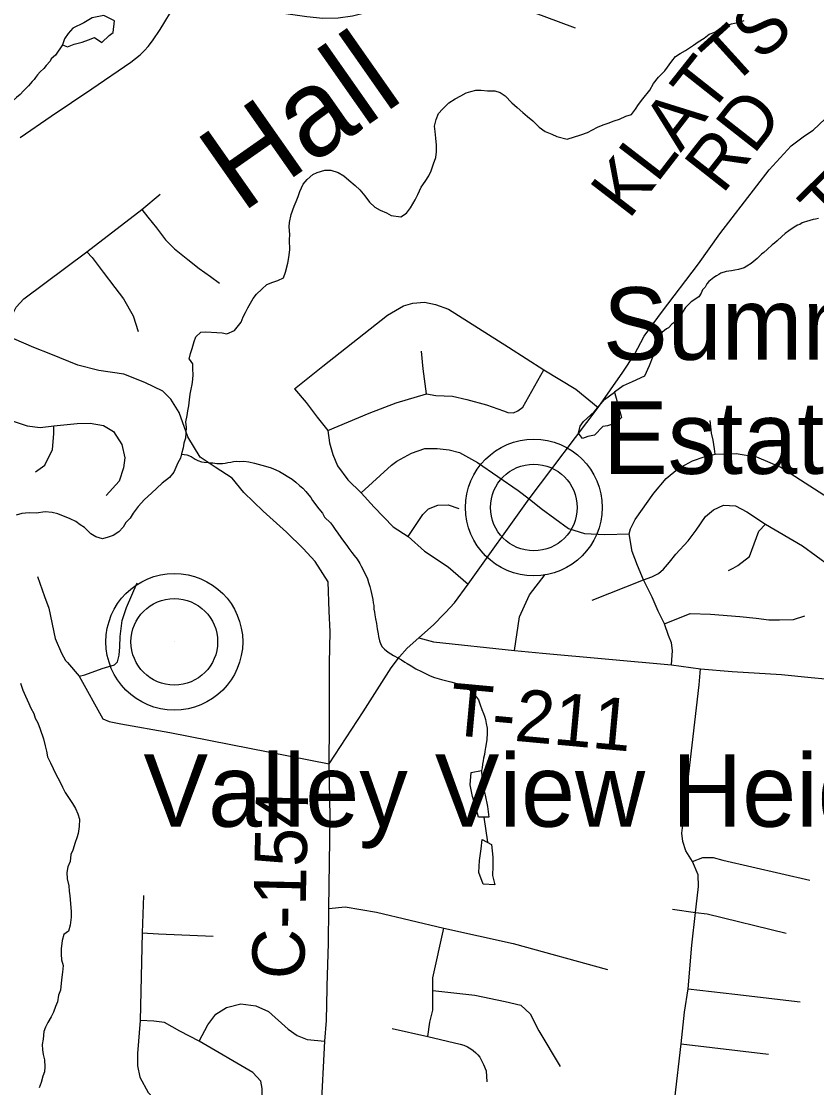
# Model space of a CAD drawing. Extents: x 0 to 34, y 0 to 22.
# Drawn here: x 6.213 to 6.645, y 17.164 to 17.744 of the extents above; entities that cross this region are included whole.
import ezdxf

# ---------------------------------------------------------------- set-up
doc = ezdxf.new("R2010")
doc.units = 0
for name, color, linetype in [('GM_X_County_Road', 7, 'Continuous'), ('GM_X_County_Road_Text', 7, 'Continuous'), ('GM_X_Minor_Lake', 7, 'Continuous'), ('GM_X_Minor_River', 7, 'Continuous'), ('GM_X_Minor_River_Text', 7, 'Continuous'), ('GM_X_Township_Road', 7, 'Continuous'), ('GM_X_Township_Road_Text', 7, 'Continuous'), ('GM_X_Unincorporated', 7, 'Continuous'), ('GM_X_Unincorporated_Location', 7, 'Continuous'), ('GM_X_Unincorporated_Text', 7, 'Continuous')]:
    doc.layers.add(name, color=color, linetype=linetype)

msp = doc.modelspace()

# ---------------------------------------------------------------- linework, layer by layer
at = {"layer": 'GM_X_County_Road'}
for points in [[(6.21206, 17.68092), (6.22902, 17.69252), (6.25117, 17.70742), (6.27244, 17.72194), (6.27744, 17.72589), (6.27986, 17.72827), (6.28173, 17.73042), (6.2842, 17.73355), (6.28826, 17.73975), (6.29651, 17.75325)], [(6.38018, 17.34004), (6.38051, 17.36122), (6.38051, 17.39483), (6.38074, 17.41186), (6.38029, 17.42306), (6.37962, 17.43919), (6.37267, 17.45017), (6.36617, 17.45734), (6.35712, 17.46614), (6.34443, 17.47751), (6.33388, 17.48773), (6.32745, 17.49547), (6.31819, 17.5016), (6.31001, 17.50705), (6.30333, 17.51798), (6.29861, 17.53124), (6.29416, 17.53849), (6.28971, 17.54294), (6.27998, 17.54756), (6.26861, 17.55217), (6.25493, 17.55415), (6.24356, 17.55712), (6.22889, 17.56305), (6.21966, 17.56668), (6.20325, 17.57373)], [(6.3792, 17.21796), (6.37922, 17.21894), (6.37984, 17.24247), (6.38003, 17.26136), (6.38077, 17.31122), (6.38018, 17.34004)], [(6.37235, 17.01941), (6.37239, 17.02043), (6.37207, 17.03968), (6.37221, 17.04345), (6.37333, 17.08511), (6.37333, 17.09592), (6.37376, 17.106), (6.37506, 17.13841), (6.37592, 17.15022), (6.37783, 17.18906), (6.37876, 17.20036), (6.3792, 17.21796)]]:
    msp.add_lwpolyline(points, dxfattribs=at)
at = {"layer": 'GM_X_Minor_Lake'}
msp.add_line((6.46432, 17.31097), (6.46634, 17.29737), dxfattribs=at)
for points in [[(6.26347, 17.74441), (6.25763, 17.74738), (6.25133, 17.74618), (6.24672, 17.74342), (6.24077, 17.7405), (6.23824, 17.73752), (6.23628, 17.73471), (6.23526, 17.7315), (6.2379, 17.7303), (6.24154, 17.73175), (6.24593, 17.7328), (6.24937, 17.73406), (6.25263, 17.73532), (6.25657, 17.73277), (6.26063, 17.73648), (6.26276, 17.73815), (6.26347, 17.74441)], [(6.53539, 17.54227), (6.53929, 17.52851), (6.536, 17.52553), (6.53161, 17.5241), (6.52913, 17.52358), (6.52467, 17.51892), (6.52105, 17.51823), (6.51799, 17.51715), (6.51596, 17.52005), (6.51679, 17.52383), (6.51855, 17.52646)], [(6.51855, 17.52646), (6.52435, 17.53166), (6.53, 17.53839), (6.53539, 17.54227)], [(6.46306, 17.33643), (6.46355, 17.32951), (6.46513, 17.32302), (6.46633, 17.31691), (6.46716, 17.31101), (6.46147, 17.31093), (6.46023, 17.31571), (6.45827, 17.32221), (6.45688, 17.3287), (6.45759, 17.33534)], [(6.4635, 17.29891), (6.46858, 17.29615), (6.4692, 17.2893), (6.46929, 17.28435), (6.46919, 17.27922), (6.47042, 17.27426), (6.46397, 17.27458), (6.46163, 17.2809), (6.46195, 17.28735), (6.46302, 17.29379)]]:
    msp.add_lwpolyline(points, dxfattribs=at)
at = {"layer": 'GM_X_Minor_River'}
for p, q in [((6.45759, 17.33534), (6.46306, 17.33643)), ((6.46302, 17.29379), (6.4635, 17.29891))]:
    msp.add_line(p, q, dxfattribs=at)
for points in [[(6.54465, 17.6935), (6.54698, 17.69631), (6.54854, 17.69894), (6.55087, 17.70194), (6.55475, 17.70681), (6.55672, 17.71039), (6.55943, 17.71376), (6.56291, 17.71731), (6.56661, 17.72257), (6.56874, 17.725), (6.57123, 17.72667), (6.57411, 17.72833), (6.57852, 17.73129), (6.58102, 17.73296), (6.58428, 17.73499), (6.58697, 17.73723), (6.59003, 17.73832), (6.59349, 17.74092), (6.59654, 17.742), (6.59921, 17.74291), (6.60245, 17.74361), (6.60607, 17.74469)], [(6.23526, 17.7315), (6.23142, 17.72576), (6.22909, 17.72374), (6.22849, 17.72261), (6.22634, 17.7202), (6.22497, 17.71853), (6.22302, 17.71669), (6.22165, 17.71502), (6.22048, 17.71372), (6.21969, 17.7126), (6.21871, 17.71149), (6.21675, 17.70907), (6.21402, 17.7063), (6.21207, 17.70445), (6.21013, 17.7028), (6.20838, 17.70113), (6.2074, 17.70002), (6.20661, 17.69872), (6.20486, 17.69686)], [(6.30407, 17.56026), (6.30489, 17.56348), (6.3057, 17.56612), (6.30672, 17.56991), (6.30771, 17.57255), (6.31041, 17.57497), (6.31307, 17.57512), (6.31913, 17.57482), (6.32197, 17.57458), (6.32462, 17.57416), (6.32882, 17.57599), (6.33232, 17.58049), (6.3335, 17.58332), (6.33469, 17.58576), (6.33606, 17.58821), (6.33899, 17.59329), (6.34075, 17.59573), (6.34364, 17.59834), (6.34634, 17.60095), (6.34959, 17.60223), (6.35226, 17.60313), (6.35532, 17.6046), (6.35651, 17.60762), (6.35774, 17.61254), (6.35836, 17.61557), (6.35882, 17.61974), (6.35873, 17.62525), (6.35878, 17.6281), (6.35847, 17.63228), (6.35871, 17.63475), (6.35955, 17.6391), (6.36114, 17.64364), (6.36233, 17.64609), (6.36333, 17.64892), (6.36432, 17.65156), (6.3661, 17.65552), (6.36823, 17.65814), (6.37132, 17.66075), (6.3738, 17.66185), (6.37781, 17.66311), (6.38122, 17.66324), (6.38518, 17.66184), (6.38818, 17.66008), (6.39098, 17.65775), (6.39434, 17.65485), (6.39695, 17.65252), (6.39974, 17.64924), (6.40214, 17.64578), (6.40513, 17.64307), (6.40794, 17.6415), (6.41152, 17.63992), (6.41396, 17.63855), (6.41925, 17.6377), (6.42232, 17.63974), (6.42446, 17.64274), (6.427, 17.64707), (6.42857, 17.64989), (6.43035, 17.65385), (6.4325, 17.65704), (6.43445, 17.66005), (6.43582, 17.66288), (6.43703, 17.66665), (6.43823, 17.67005), (6.43866, 17.67309), (6.43873, 17.67688), (6.43823, 17.68069), (6.43792, 17.68431), (6.43759, 17.68716), (6.43842, 17.69076), (6.4398, 17.69396), (6.44193, 17.6964), (6.44541, 17.69976), (6.44886, 17.70198), (6.45192, 17.70364), (6.4548, 17.7053), (6.45728, 17.70601), (6.46013, 17.70672), (6.46298, 17.70668), (6.46639, 17.70643), (6.47037, 17.70636), (6.4732, 17.70555), (6.476, 17.7036), (6.47954, 17.69993), (6.48252, 17.69722), (6.4857, 17.69451), (6.48813, 17.69238), (6.49112, 17.69004), (6.49447, 17.68657), (6.49784, 17.68423), (6.50142, 17.68284), (6.50405, 17.68146), (6.50971, 17.68004), (6.51715, 17.68238), (6.52077, 17.68365), (6.52632, 17.68659), (6.52938, 17.68787), (6.53205, 17.68877), (6.5353, 17.69005), (6.53816, 17.69095), (6.5416, 17.6926), (6.54465, 17.6935)], [(6.64639, 17.63693), (6.64486, 17.63659), (6.64353, 17.63625), (6.63989, 17.63521), (6.63874, 17.63486), (6.63759, 17.63451), (6.63624, 17.6336), (6.63509, 17.63325), (6.63317, 17.63216), (6.63027, 17.63015), (6.62833, 17.62868), (6.62658, 17.62702), (6.62405, 17.62481), (6.6225, 17.62352), (6.62134, 17.6226), (6.61861, 17.62002), (6.61667, 17.61836), (6.61551, 17.61744), (6.61317, 17.61504), (6.60988, 17.61247), (6.60756, 17.61101), (6.60602, 17.6101), (6.60295, 17.60905), (6.60086, 17.60872), (6.59914, 17.60839), (6.59761, 17.60824), (6.59628, 17.60808), (6.59341, 17.60721), (6.59225, 17.60648), (6.5909, 17.60576), (6.58955, 17.60484), (6.58684, 17.60264), (6.58566, 17.60134), (6.58486, 17.59947), (6.5833, 17.59799), (6.58269, 17.5963), (6.58131, 17.59425), (6.57725, 17.59151), (6.57413, 17.58836), (6.57255, 17.58594), (6.57193, 17.58406), (6.56864, 17.58149), (6.56784, 17.58018), (6.56669, 17.57945), (6.56493, 17.57741), (6.56377, 17.57687), (6.56261, 17.57595), (6.56145, 17.57504), (6.56027, 17.57355), (6.55928, 17.57187), (6.55846, 17.56961), (6.55762, 17.5666), (6.55722, 17.56547), (6.55699, 17.56396), (6.55658, 17.56283), (6.55636, 17.5617)], [(6.30407, 17.56026), (6.30595, 17.55772), (6.30588, 17.55488), (6.30599, 17.55202), (6.30592, 17.54917), (6.30547, 17.54652), (6.30503, 17.54406), (6.30439, 17.54123), (6.30412, 17.53819), (6.30366, 17.53497), (6.30321, 17.53213), (6.30276, 17.52968), (6.30211, 17.52627), (6.3024, 17.52303), (6.30233, 17.52018), (6.30207, 17.51734), (6.30123, 17.51451), (6.30079, 17.51205), (6.29995, 17.50884), (6.29932, 17.50638), (6.29793, 17.50395), (6.29692, 17.50131), (6.29572, 17.49888), (6.29336, 17.4959), (6.28931, 17.49277), (6.28367, 17.48741), (6.27979, 17.4839), (6.27629, 17.48019), (6.27354, 17.47646), (6.27195, 17.47384), (6.26962, 17.47143), (6.26822, 17.4688), (6.26589, 17.46639), (6.2628, 17.46438), (6.25994, 17.46351), (6.25688, 17.46245), (6.25331, 17.46368), (6.25051, 17.46528), (6.24718, 17.4686), (6.24476, 17.47018), (6.24234, 17.47195), (6.23935, 17.47336), (6.2326, 17.4762), (6.22958, 17.47685), (6.2258, 17.47714), (6.22086, 17.47651), (6.21707, 17.47661), (6.21309, 17.47634), (6.21003, 17.47547)], [(6.55636, 17.5617), (6.55429, 17.55672), (6.55189, 17.55106), (6.545, 17.54797), (6.54021, 17.54579), (6.53539, 17.54227)], [(6.2999, 17.50865), (6.30284, 17.50824), (6.30511, 17.50725), (6.30737, 17.50588), (6.30887, 17.50509), (6.31076, 17.50449), (6.31228, 17.50427), (6.31437, 17.50404), (6.3157, 17.50383), (6.31703, 17.5038), (6.31911, 17.50358), (6.32215, 17.50352), (6.32368, 17.50369), (6.3252, 17.50404), (6.32673, 17.5042), (6.32825, 17.50456), (6.32978, 17.50472), (6.33168, 17.50469), (6.33377, 17.50484), (6.33661, 17.50441), (6.33965, 17.50379), (6.3457, 17.50216), (6.34873, 17.50116), (6.35118, 17.50016), (6.35325, 17.49918), (6.36003, 17.49506), (6.36209, 17.49331), (6.36415, 17.49157), (6.36584, 17.49002), (6.36752, 17.48827), (6.3692, 17.48634), (6.37031, 17.48499), (6.37124, 17.48345), (6.37458, 17.47883), (6.37663, 17.47651), (6.37774, 17.4744), (6.38092, 17.4713), (6.38203, 17.46976), (6.38352, 17.46764), (6.385, 17.46553), (6.38667, 17.46321), (6.38797, 17.46129), (6.38983, 17.45897), (6.39095, 17.45724), (6.39262, 17.45512), (6.39392, 17.45339), (6.39541, 17.45146), (6.39689, 17.44915), (6.39763, 17.44762), (6.39855, 17.44608), (6.40112, 17.44071), (6.40166, 17.4388), (6.40238, 17.4365), (6.40291, 17.4344), (6.40397, 17.42944), (6.40413, 17.42772), (6.40449, 17.4262), (6.40464, 17.42429), (6.405, 17.42257), (6.40516, 17.42124), (6.40551, 17.41895), (6.40603, 17.41647), (6.40637, 17.41361), (6.40689, 17.41075), (6.40706, 17.40941), (6.40758, 17.40693), (6.40831, 17.40502), (6.40905, 17.40367), (6.41036, 17.40251), (6.41242, 17.40076), (6.41524, 17.399), (6.41788, 17.39762), (6.41958, 17.39664), (6.42146, 17.39547), (6.42277, 17.39468), (6.42484, 17.39332), (6.42748, 17.39175), (6.4305, 17.39036), (6.43521, 17.388), (6.43747, 17.38701), (6.4388, 17.38661), (6.44145, 17.38599), (6.44637, 17.38476), (6.44845, 17.38415), (6.45072, 17.38335), (6.45261, 17.38275), (6.45393, 17.38216), (6.45543, 17.38118), (6.45712, 17.37982), (6.45843, 17.37865), (6.46048, 17.37634), (6.46141, 17.3748), (6.46231, 17.37212), (6.46322, 17.36963), (6.46414, 17.36752), (6.46468, 17.36599), (6.46522, 17.36427), (6.46575, 17.36198), (6.46628, 17.3595), (6.46624, 17.35684), (6.46598, 17.35304)], [(6.21241, 17.38397), (6.21363, 17.38014), (6.21507, 17.37687), (6.21686, 17.37283), (6.21793, 17.37033), (6.21956, 17.36743), (6.22025, 17.36494), (6.2217, 17.36243), (6.22294, 17.35898), (6.22489, 17.35361), (6.22574, 17.34978), (6.22642, 17.34691), (6.2271, 17.34385), (6.22872, 17.34058), (6.23159, 17.33442), (6.23376, 17.33037), (6.2352, 17.32729), (6.23664, 17.3244), (6.23847, 17.32169), (6.24065, 17.31841)], [(6.46598, 17.35304), (6.46534, 17.34886), (6.46493, 17.34678), (6.46471, 17.34507), (6.46429, 17.34318), (6.46408, 17.34166), (6.46367, 17.33995), (6.46345, 17.33787), (6.46306, 17.33643)], [(6.24065, 17.31841), (6.24229, 17.3157), (6.24354, 17.31282), (6.24441, 17.30994), (6.24431, 17.30595), (6.24364, 17.30217), (6.24301, 17.29971), (6.242, 17.29727), (6.24076, 17.29312), (6.23975, 17.29068), (6.23927, 17.28689), (6.23806, 17.28407), (6.2376, 17.28085), (6.2377, 17.27742), (6.23855, 17.2736), (6.23885, 17.27074), (6.23917, 17.26826), (6.2399, 17.25969), (6.23982, 17.25665), (6.23933, 17.25229), (6.23848, 17.24889), (6.23597, 17.24724), (6.23494, 17.24385), (6.23444, 17.2393), (6.23437, 17.23645), (6.23467, 17.2334), (6.23554, 17.23034), (6.23525, 17.22673), (6.2348, 17.22389), (6.23453, 17.22067), (6.23405, 17.21688), (6.23303, 17.21405), (6.23237, 17.21046), (6.23136, 17.20802), (6.23033, 17.20481), (6.22894, 17.20238), (6.22715, 17.19919), (6.22595, 17.19675), (6.22494, 17.19431), (6.22465, 17.19013), (6.22419, 17.18729), (6.22431, 17.18444), (6.22462, 17.18177), (6.2253, 17.1789), (6.22559, 17.17509), (6.22533, 17.17244), (6.22451, 17.16999), (6.22366, 17.16659), (6.22245, 17.16377)]]:
    msp.add_lwpolyline(points, dxfattribs=at)
at = {"layer": 'GM_X_Township_Road'}
for p, q in [((6.64354, 17.68488), (6.65013, 17.69113)), ((6.57174, 17.18764), (6.61923, 17.18195))]:
    msp.add_line(p, q, dxfattribs=at)
for points in [[(6.30348, 17.76452), (6.30715, 17.76232), (6.30972, 17.76145), (6.31795, 17.76003), (6.323, 17.75688), (6.3275, 17.75489), (6.33408, 17.75248), (6.34106, 17.75101), (6.35295, 17.74906), (6.36805, 17.74686), (6.37675, 17.74592), (6.38509, 17.74614), (6.39287, 17.74712), (6.40696, 17.75064), (6.41874, 17.75296), (6.43066, 17.75547), (6.43976, 17.75578), (6.45168, 17.75516), (6.46674, 17.75327), (6.4852, 17.75135), (6.49704, 17.74693), (6.51412, 17.74072)], [(6.44349, 17.42235), (6.4484, 17.42761), (6.45595, 17.43777), (6.48897, 17.48422), (6.52666, 17.53398), (6.54, 17.55315), (6.54635, 17.56287), (6.5517, 17.57278), (6.56102, 17.58566), (6.58124, 17.61223), (6.59272, 17.62849), (6.61962, 17.66346), (6.63159, 17.6765), (6.63885, 17.68186), (6.64354, 17.68488)], [(6.16082, 17.45344), (6.1778, 17.49481), (6.18686, 17.51575), (6.19395, 17.53239), (6.19625, 17.53849), (6.19865, 17.543), (6.19918, 17.54886), (6.19882, 17.55351), (6.19854, 17.55926), (6.19937, 17.56419), (6.20325, 17.57373), (6.20584, 17.58034), (6.20995, 17.58865), (6.21415, 17.59321), (6.24846, 17.61867), (6.2784, 17.64185), (6.28825, 17.65007)], [(6.2784, 17.64185), (6.28155, 17.63755), (6.28627, 17.63182), (6.29126, 17.62535), (6.29616, 17.62035), (6.30328, 17.61462), (6.30948, 17.60963), (6.31567, 17.60528), (6.32066, 17.60177)], [(6.24846, 17.61867), (6.25129, 17.61557), (6.25732, 17.60772), (6.26361, 17.59932), (6.26836, 17.59321), (6.27356, 17.58399), (6.2763, 17.57532)], [(6.36138, 17.54423), (6.37684, 17.55652), (6.41193, 17.58428), (6.42066, 17.58943), (6.42581, 17.59082), (6.43215, 17.59141), (6.4381, 17.59003), (6.44525, 17.58752), (6.47781, 17.56684), (6.49698, 17.55454), (6.51443, 17.54403), (6.52666, 17.53398)], [(6.43314, 17.54145), (6.43136, 17.55513), (6.43057, 17.56465)], [(6.37948, 17.52152), (6.40202, 17.53095), (6.41669, 17.5365), (6.43314, 17.54145), (6.43823, 17.54053), (6.44731, 17.54022), (6.45519, 17.53844), (6.46587, 17.53542), (6.47503, 17.53226), (6.47746, 17.53122), (6.48048, 17.53112), (6.48298, 17.53218), (6.48569, 17.53418), (6.49698, 17.55454)], [(6.36138, 17.54423), (6.36772, 17.5367), (6.37367, 17.52876), (6.37948, 17.52152), (6.38041, 17.51469), (6.3822, 17.50835), (6.38477, 17.5022), (6.39032, 17.49467), (6.39766, 17.48753), (6.40479, 17.4798), (6.4151, 17.46909), (6.42323, 17.46374), (6.43215, 17.45581), (6.44504, 17.44728), (6.45595, 17.43777)], [(6.19395, 17.53239), (6.20675, 17.52705), (6.21587, 17.52399), (6.22296, 17.52316), (6.23054, 17.52399), (6.24323, 17.52531), (6.25015, 17.52547), (6.2574, 17.52415), (6.26301, 17.52086), (6.26741, 17.5138), (6.26911, 17.50668), (6.26845, 17.50108), (6.26597, 17.49399), (6.25889, 17.48608)], [(6.22055, 17.49903), (6.22559, 17.50256), (6.22971, 17.51113), (6.23054, 17.5197), (6.23054, 17.52399)], [(6.59024, 17.5086), (6.58997, 17.51148), (6.58915, 17.51628), (6.58832, 17.51998), (6.5875, 17.52684)], [(6.39766, 17.48753), (6.41423, 17.50258), (6.41714, 17.50476), (6.42502, 17.50914), (6.43235, 17.51171), (6.43895, 17.51162), (6.44555, 17.51102), (6.45117, 17.5095), (6.46101, 17.50404), (6.483, 17.48886), (6.48897, 17.48422)], [(6.56649, 17.39393), (6.56704, 17.40178), (6.56657, 17.40582), (6.56486, 17.40986), (6.56268, 17.41623), (6.55927, 17.42307), (6.556, 17.43069), (6.55119, 17.44017), (6.54808, 17.44809), (6.54513, 17.45571), (6.54354, 17.46518), (6.54416, 17.46798), (6.54679, 17.47302), (6.55689, 17.48745), (6.56366, 17.49542), (6.56994, 17.50064), (6.5779, 17.50503), (6.58421, 17.50723), (6.59024, 17.5086), (6.60163, 17.50901), (6.61274, 17.50723), (6.62604, 17.50147), (6.66513, 17.47623), (6.69633, 17.44871)], [(6.48897, 17.48422), (6.49554, 17.47912), (6.51049, 17.46817), (6.51917, 17.4655), (6.53021, 17.46488), (6.54354, 17.46518)], [(6.42323, 17.46374), (6.43116, 17.47583), (6.43424, 17.47881), (6.43943, 17.48079), (6.44504, 17.48099), (6.45074, 17.47895)], [(6.52337, 17.42913), (6.55119, 17.44017), (6.55585, 17.44188), (6.55942, 17.44374), (6.56206, 17.44592), (6.56533, 17.4498), (6.5689, 17.45415), (6.57553, 17.46141), (6.57989, 17.46716), (6.58491, 17.47466), (6.58942, 17.47839), (6.59485, 17.48088), (6.60138, 17.48057), (6.60744, 17.47715), (6.6177, 17.47047), (6.63774, 17.45866), (6.65266, 17.44778), (6.66447, 17.43659), (6.67665, 17.42587)], [(6.59749, 17.44528), (6.59999, 17.44653), (6.6025, 17.44796), (6.6089, 17.45298), (6.61398, 17.46677), (6.6177, 17.47047)], [(6.22154, 17.44199), (6.22542, 17.43109), (6.22774, 17.42475), (6.23117, 17.40827), (6.23465, 17.40032), (6.23689, 17.39629), (6.23784, 17.39517)], [(6.48106, 17.40172), (6.48374, 17.42012), (6.48918, 17.43209), (6.49773, 17.44312)], [(6.24417, 17.38777), (6.24731, 17.38844), (6.25683, 17.39191), (6.26351, 17.39389), (6.26506, 17.39557), (6.26607, 17.39917), (6.26634, 17.40372), (6.26663, 17.40942), (6.26758, 17.41813), (6.27005, 17.42508), (6.27577, 17.43855)], [(6.38018, 17.34004), (6.39883, 17.36838), (6.41389, 17.39234), (6.41847, 17.39825), (6.42274, 17.40309), (6.42901, 17.40872), (6.43709, 17.41568), (6.44284, 17.42165), (6.44349, 17.42235)], [(6.56268, 17.41623), (6.57667, 17.42183), (6.5877, 17.42152), (6.60371, 17.42027), (6.61257, 17.41934), (6.61941, 17.41841), (6.62516, 17.41841), (6.63279, 17.41857), (6.63899, 17.42058)], [(6.42901, 17.40872), (6.43692, 17.40637), (6.48106, 17.40172), (6.49624, 17.40022), (6.56649, 17.39393), (6.5823, 17.39176), (6.59952, 17.39028), (6.6264, 17.38873), (6.64256, 17.38702), (6.65798, 17.38557), (6.66268, 17.38517)], [(6.23784, 17.39517), (6.24417, 17.38777), (6.25705, 17.36447), (6.26053, 17.36301), (6.26691, 17.36178), (6.29358, 17.35707), (6.38018, 17.34004)], [(6.57962, 17.25915), (6.58048, 17.26701), (6.58125, 17.27324), (6.58099, 17.27964), (6.57792, 17.28681), (6.57433, 17.2927), (6.57263, 17.29773), (6.5722, 17.30234), (6.57297, 17.30951), (6.58158, 17.38303), (6.5823, 17.39176)], [(6.57792, 17.28681), (6.58355, 17.28903), (6.58918, 17.28903), (6.59439, 17.28766), (6.64176, 17.27665)], [(6.2792, 17.26833), (6.27843, 17.24805), (6.27735, 17.20036), (6.27595, 17.1824), (6.27595, 17.17574), (6.27719, 17.16955), (6.28184, 17.16119), (6.28989, 17.15236), (6.295, 17.14648), (6.30011, 17.14323), (6.30676, 17.14059), (6.32085, 17.13951), (6.34315, 17.1392), (6.37506, 17.13841)], [(6.38003, 17.26136), (6.38891, 17.26229), (6.40598, 17.25932), (6.4427, 17.2506), (6.48026, 17.24227), (6.53173, 17.22809)], [(6.56356, 17.10935), (6.5657, 17.13647), (6.56826, 17.15784), (6.57174, 17.18764), (6.57351, 17.20493), (6.57553, 17.2176), (6.57758, 17.2414), (6.57962, 17.25915)], [(6.56698, 17.2609), (6.57962, 17.25915), (6.58586, 17.25838), (6.62888, 17.24789)], [(6.4339, 17.19159), (6.4351, 17.19941), (6.4367, 17.2059), (6.4367, 17.2166), (6.43658, 17.22352), (6.4427, 17.2506)], [(6.27843, 17.24805), (6.28741, 17.24758), (6.31714, 17.24619)], [(6.4367, 17.2166), (6.45953, 17.21422), (6.47605, 17.21065), (6.48444, 17.20868), (6.48964, 17.20404), (6.49428, 17.19477), (6.50596, 17.17529)], [(6.57553, 17.2176), (6.60087, 17.21464), (6.6364, 17.2105)], [(6.30955, 17.18906), (6.3142, 17.19804), (6.31862, 17.20375), (6.32441, 17.20733), (6.33216, 17.20934), (6.34036, 17.20841), (6.34733, 17.20516), (6.35786, 17.19556), (6.36281, 17.19215), (6.36823, 17.18999), (6.37783, 17.18906)], [(6.34315, 17.1392), (6.34377, 17.15654), (6.34377, 17.16336), (6.34315, 17.16738), (6.33866, 17.17203), (6.30955, 17.18906), (6.29902, 17.19448), (6.29066, 17.19928), (6.28478, 17.19989), (6.27735, 17.20036)], [(6.41451, 17.19607), (6.4339, 17.19159), (6.45151, 17.18752), (6.45353, 17.18691), (6.45555, 17.18607), (6.45728, 17.18499), (6.4586, 17.18407), (6.4601, 17.18277), (6.46115, 17.18166), (6.4622, 17.18034), (6.46422, 17.17633), (6.46561, 17.17288), (6.46598, 17.16704)]]:
    msp.add_lwpolyline(points, dxfattribs=at)
at = {"layer": 'GM_X_Unincorporated'}
for centre, radius in [((6.49161, 17.47959), 0.0372), ((6.49161, 17.47959), 0.02358), ((6.29601, 17.40648), 0.0372), ((6.29601, 17.40648), 0.02358)]:
    msp.add_circle(centre, radius, dxfattribs=at)
at = {"layer": 'GM_X_Unincorporated_Location'}
for p, q in [((6.49161, 17.47959), (6.49161, 17.47959)), ((6.29601, 17.40648), (6.29601, 17.40648))]:
    msp.add_line(p, q, dxfattribs=at)

# ---------------------------------------------------------------- texts
at = {"layer": 'GM_X_County_Road_Text'}
msp.add_text('C-154', height=0.028409, rotation=88.71966, dxfattribs=at).set_placement((6.36659, 17.22257))
at = {"layer": 'GM_X_Minor_River_Text'}
msp.add_text('Hall', height=0.047352, rotation=35.00421, dxfattribs=at).set_placement((6.33262, 17.63953))
at = {"layer": 'GM_X_Township_Road_Text'}
for s, height, rotation, p in [('S', 0.02841, 39.59263, (6.61451, 17.72201)), ('T', 0.02841, 42.19585, (6.59902, 17.70796)), ('T', 0.02841, 51.62999, (6.58668, 17.6922)), ('RD', 0.028409, 51.86581, (6.59419, 17.64956)), ('A', 0.02841, 52.38476, (6.57148, 17.67248)), ('L', 0.02841, 52.39038, (6.55851, 17.65564)), ('K', 0.02841, 52.38987, (6.54325, 17.63584)), ('T', 0.02841, 44.66969, (6.65346, 17.62703)), ('T-211', 0.028409, 354.73048, (6.44484, 17.35592))]:
    msp.add_text(s, height=height, rotation=rotation, dxfattribs=at).set_placement(p)
at = {"layer": 'GM_X_Unincorporated_Text'}
for s, height, p in [('Summerside', 0.039489, (6.5292, 17.55998)), ('Estates', 0.039489, (6.5292, 17.49789)), ('Valley View Heights', 0.0394886, (6.2792, 17.30581))]:
    msp.add_text(s, height=height, rotation=0.00001, dxfattribs=at).set_placement(p)

doc.saveas('drawing.dxf')
